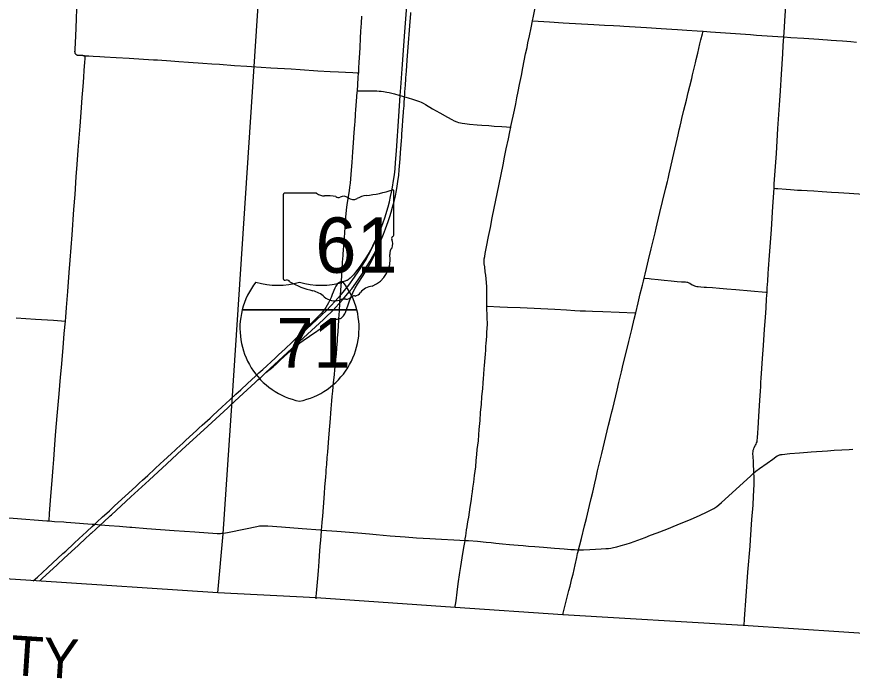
# Model space of a CAD drawing. Extents: x 1815539 to 1947826, y 273303 to 993194.
# Drawn here: x 1868609 to 1889640, y 855404 to 872057 of the extents above; entities that cross this region are included whole.
import ezdxf

# ---------------------------------------------------------------- set-up
doc = ezdxf.new("R2010")
doc.units = 0
for name, color, linetype in [('GM_X_Adjacent_County_Text', 7, 'Continuous'), ('GM_X_County', 7, 'Continuous'), ('GM_X_County_Road', 7, 'Continuous'), ('GM_X_Interchange_Ramps', 7, 'Continuous'), ('GM_X_Interstate_Route', 7, 'Continuous'), ('GM_X_Interstate_Shield', 7, 'Continuous'), ('GM_X_State_Route', 7, 'Continuous'), ('GM_X_Township', 7, 'Continuous'), ('GM_X_Township_Road', 7, 'Continuous'), ('SC_Shading3', 7, 'Continuous')]:
    doc.layers.add(name, color=color, linetype=linetype)

msp = doc.modelspace()

# ---------------------------------------------------------------- linework, layer by layer
at = {"layer": 'GM_X_County'}
msp.add_lwpolyline([(1890695, 856480), (1886895, 856734), (1882352, 856998), (1879641, 857188), (1876143, 857428), (1873671, 857558), (1869100, 857855), (1863977, 858188), (1861827, 858324), (1850615, 859080), (1848752, 859146), (1848787, 859601), (1848864, 860810), (1849106, 864311), (1849634, 872258), (1850017, 877290), (1850147, 879854), (1845959, 880135)], dxfattribs=at)
at = {"layer": 'GM_X_County_Road'}
for points in [[(1887918, 871548), (1887924, 871662), (1887953, 872087), (1887976, 872429), (1887990, 872658), (1888004, 872870), (1888017, 873050), (1888042, 873443), (1888071, 873901), (1888119, 874654), (1888128, 874784)], [(1881591, 871952), (1881615, 872067), (1881668, 872319), (1881683, 872399), (1881701, 872487), (1881717, 872568), (1881734, 872660), (1881750, 872737), (1881780, 872881), (1881800, 872979), (1881819, 873079), (1881833, 873160), (1881843, 873242), (1881852, 873340), (1881855, 873411)], [(1870298, 871074), (1870294, 871075), (1870289, 871076), (1870285, 871076), (1870282, 871076), (1870275, 871077), (1870264, 871078), (1870241, 871078), (1870169, 871081), (1870146, 871083), (1870141, 871084), (1870133, 871086), (1870126, 871089), (1870119, 871092), (1870112, 871096), (1870105, 871102), (1870098, 871108), (1870093, 871114), (1870089, 871121), (1870084, 871129), (1870081, 871137), (1870078, 871146), (1870077, 871153), (1870076, 871158), (1870076, 871164), (1870075, 871170), (1870075, 871179), (1870076, 871207), (1870077, 871235), (1870095, 871573), (1870103, 871769), (1870115, 872014), (1870126, 872244)], [(1881042, 869278), (1881045, 869291), (1881134, 869708), (1881169, 869868), (1881199, 870012), (1881232, 870173), (1881268, 870350), (1881314, 870575), (1881350, 870769), (1881384, 870946), (1881419, 871123), (1881453, 871283), (1881477, 871396), (1881513, 871572), (1881555, 871781), (1881591, 871952)], [(1881591, 871952), (1882016, 871925), (1882365, 871907), (1883139, 871858), (1883401, 871847), (1883626, 871836), (1883788, 871828), (1883887, 871823), (1884459, 871786), (1884826, 871761)], [(1884826, 871761), (1884966, 871751), (1885097, 871742), (1885244, 871732), (1885478, 871716), (1885735, 871700), (1885885, 871690)], [(1885694, 870900), (1885712, 870976), (1885750, 871136), (1885807, 871375), (1885830, 871471), (1885868, 871630), (1885885, 871690)], [(1887670, 867741), (1887677, 867850), (1887700, 868177), (1887729, 868618), (1887770, 869240), (1887808, 869829), (1887830, 870189), (1887856, 870614), (1887891, 871122), (1887904, 871334), (1887918, 871548)], [(1869835, 864397), (1869843, 864490), (1869862, 864735), (1869893, 865144), (1869930, 865619), (1869952, 865930), (1870002, 866568), (1870050, 867206), (1870077, 867582), (1870109, 868024), (1870132, 868335), (1870159, 868695), (1870204, 869301), (1870230, 869644), (1870258, 870020), (1870278, 870299), (1870295, 870528), (1870307, 870708), (1870323, 870904), (1870331, 871007), (1870332, 871017), (1870333, 871028), (1870333, 871032), (1870333, 871037), (1870333, 871040), (1870332, 871044), (1870332, 871045), (1870332, 871048), (1870331, 871050), (1870330, 871053), (1870329, 871055), (1870327, 871058), (1870326, 871060), (1870325, 871061), (1870323, 871063), (1870321, 871064), (1870319, 871066), (1870317, 871067), (1870315, 871068), (1870313, 871069), (1870310, 871070), (1870308, 871071), (1870298, 871074)], [(1870298, 871074), (1870424, 871069), (1870533, 871063), (1870699, 871054), (1870822, 871047), (1871116, 871029), (1871443, 871010), (1871803, 870988), (1872048, 870973), (1872150, 870968), (1872485, 870945), (1872686, 870930), (1872931, 870913), (1873291, 870888), (1873519, 870873), (1873716, 870860), (1874091, 870831), (1874402, 870810), (1874516, 870803)], [(1874516, 870803), (1875007, 870772), (1875514, 870742), (1875743, 870727), (1876184, 870698), (1876495, 870679), (1876707, 870666), (1876887, 870659), (1877067, 870651), (1877182, 870646), (1877216, 870645)], [(1884401, 865479), (1884424, 865573), (1884458, 865716), (1884513, 865939), (1884579, 866210), (1884651, 866513), (1884679, 866621), (1884706, 866733), (1884733, 866844), (1884766, 866988), (1884800, 867132), (1884865, 867402), (1884949, 867753), (1884988, 867913), (1885002, 867976), (1885032, 868104), (1885067, 868248), (1885126, 868503), (1885254, 869080), (1885283, 869208), (1885306, 869303), (1885334, 869415), (1885353, 869494), (1885403, 869701), (1885465, 869956), (1885513, 870147), (1885551, 870307), (1885598, 870498), (1885621, 870593), (1885694, 870900)], [(1880446, 864770), (1880445, 864839), (1880441, 865118), (1880441, 865256), (1880436, 865364), (1880425, 865461), (1880415, 865553), (1880404, 865637), (1880388, 865760), (1880378, 865837), (1880375, 865898), (1880378, 865959), (1880388, 866024), (1880401, 866097), (1880436, 866266), (1880487, 866526), (1880531, 866751), (1880580, 866992), (1880753, 867844), (1880849, 868326), (1880889, 868519), (1880930, 868728), (1880983, 868985), (1881019, 869162), (1881042, 869278)], [(1887494, 865122), (1887497, 865170), (1887500, 865235), (1887511, 865399), (1887526, 865595), (1887533, 865708), (1887559, 866050), (1887573, 866263), (1887603, 866704), (1887641, 867277), (1887670, 867741)], [(1884190, 864602), (1884252, 864855), (1884305, 865078), (1884359, 865302), (1884382, 865397), (1884401, 865479)], [(1887166, 860572), (1887164, 860625), (1887155, 860789), (1887150, 860871), (1887144, 860969), (1887141, 861068), (1887142, 861101), (1887145, 861134), (1887149, 861150), (1887153, 861166), (1887159, 861182), (1887173, 861212), (1887206, 861269), (1887221, 861298), (1887233, 861328), (1887242, 861359), (1887248, 861390), (1887254, 861455), (1887262, 861586), (1887268, 861701), (1887286, 861995), (1887312, 862404), (1887327, 862634), (1887335, 862748), (1887342, 862862), (1887349, 862961), (1887366, 863206), (1887382, 863451), (1887404, 863779), (1887432, 864188), (1887452, 864482), (1887469, 864728), (1887483, 864957), (1887494, 865122)], [(1880367, 863051), (1880377, 863199), (1880383, 863268), (1880391, 863382), (1880397, 863469), (1880406, 863567), (1880414, 863666), (1880419, 863752), (1880426, 863840), (1880432, 863919), (1880440, 864028), (1880446, 864115), (1880453, 864206), (1880455, 864322), (1880453, 864484), (1880446, 864770)], [(1868595, 864476), (1869081, 864445), (1869537, 864416), (1869835, 864397)], [(1869425, 859366), (1869437, 859552), (1869463, 859879), (1869479, 860092), (1869503, 860386), (1869527, 860714), (1869541, 860910), (1869571, 861286), (1869588, 861515), (1869606, 861727), (1869637, 862103), (1869675, 862561), (1869711, 862986), (1869732, 863231), (1869775, 863722), (1869807, 864081), (1869835, 864397)], [(1882749, 858641), (1882781, 858766), (1882823, 858927), (1882904, 859244), (1882948, 859428), (1883026, 859753), (1883068, 859929), (1883106, 860089), (1883158, 860312), (1883190, 860461), (1883229, 860629), (1883269, 860791), (1883333, 861063), (1883508, 861779), (1883548, 861938), (1883592, 862113), (1883612, 862192), (1883721, 862655), (1883766, 862846), (1883830, 863118), (1883877, 863309), (1883965, 863676), (1884016, 863883), (1884089, 864186), (1884150, 864441), (1884190, 864602)], [(1879893, 858874), (1879899, 858914), (1879910, 858992), (1879918, 859061), (1879931, 859139), (1879943, 859213), (1879959, 859293), (1879975, 859388), (1879986, 859464), (1880023, 859712), (1880035, 859806), (1880053, 859910), (1880067, 859997), (1880081, 860098), (1880092, 860193), (1880111, 860342), (1880134, 860505), (1880161, 860729), (1880175, 860889), (1880189, 861041), (1880201, 861164), (1880228, 861384), (1880242, 861531), (1880253, 861663), (1880270, 861893), (1880286, 862093), (1880305, 862302), (1880320, 862485), (1880339, 862702), (1880350, 862834), (1880360, 862959), (1880366, 863040), (1880367, 863051)], [(1887166, 860572), (1887216, 860614), (1887308, 860683), (1887494, 860818), (1887640, 860924), (1887720, 860982), (1887748, 861000), (1887777, 861016), (1887808, 861028), (1887824, 861033), (1887840, 861037), (1887873, 861041), (1888069, 861059), (1888315, 861078), (1888511, 861093), (1888609, 861101), (1889018, 861133), (1889182, 861145), (1889378, 861158), (1889558, 861167), (1889657, 861171)], [(1882749, 858641), (1882876, 858641), (1883037, 858646), (1883179, 858653), (1883316, 858659), (1883436, 858668), (1883501, 858674), (1883566, 858683), (1883630, 858695), (1883710, 858714), (1883820, 858744), (1883946, 858781), (1884055, 858817), (1884240, 858883), (1884425, 858950), (1884563, 859003), (1884731, 859068), (1884976, 859162), (1885236, 859265), (1885584, 859409), (1885793, 859503), (1885987, 859592), (1886107, 859652), (1886158, 859681), (1886205, 859710), (1886235, 859732), (1886284, 859770), (1886345, 859827), (1887081, 860494), (1887166, 860572)], [(1886918, 856737), (1886925, 856900), (1886968, 857475), (1887012, 858072), (1887069, 858727), (1887080, 858891), (1887115, 859398), (1887142, 859758), (1887156, 859987), (1887164, 860134), (1887171, 860293), (1887170, 860478), (1887166, 860572)], [(1861916, 859928), (1862629, 859873), (1863120, 859837), (1864150, 859761), (1864739, 859716), (1865507, 859658), (1865802, 859636), (1865998, 859622), (1866227, 859604), (1866505, 859582), (1866652, 859574), (1866832, 859561), (1867127, 859537), (1867486, 859512), (1868517, 859434), (1869367, 859370), (1869425, 859366)], [(1869425, 859366), (1869563, 859355), (1869793, 859339), (1869857, 859334)], [(1869857, 859334), (1869972, 859325), (1870512, 859285), (1870571, 859280), (1870708, 859269), (1870720, 859268), (1870937, 859253), (1871199, 859232), (1871452, 859211)], [(1871452, 859211), (1871509, 859207), (1871885, 859178), (1872572, 859126), (1873096, 859088), (1873652, 859052), (1873735, 859052), (1873770, 859055)], [(1873770, 859055), (1873817, 859059), (1873914, 859075), (1874364, 859169), (1874653, 859228), (1874683, 859233), (1874719, 859239), (1874747, 859242), (1874759, 859243), (1874778, 859244), (1874831, 859245), (1874929, 859242), (1875273, 859215), (1875796, 859173), (1876256, 859137), (1876281, 859135)], [(1876281, 859135), (1876663, 859106), (1877195, 859066), (1877490, 859039), (1877653, 859024), (1878012, 858994), (1878385, 858961), (1878670, 858941), (1879005, 858919), (1879153, 858913), (1879766, 858880), (1879893, 858874)], [(1879641, 857189), (1879648, 857220), (1879655, 857263), (1879670, 857355), (1879696, 857575), (1879722, 857780), (1879765, 858069), (1879788, 858222), (1879825, 858438), (1879867, 858697), (1879885, 858819), (1879893, 858874)], [(1879893, 858874), (1879982, 858869), (1880208, 858853), (1880429, 858833), (1880554, 858821), (1880668, 858808), (1880755, 858798), (1880836, 858790), (1881016, 858774), (1881229, 858754), (1881359, 858743), (1881425, 858738), (1881490, 858733), (1881654, 858720), (1881866, 858702), (1882144, 858679), (1882275, 858668), (1882389, 858660), (1882552, 858648), (1882650, 858642), (1882716, 858641), (1882749, 858641)], [(1882360, 857020), (1882365, 857041), (1882508, 857614), (1882537, 857726), (1882584, 857918), (1882612, 858029), (1882663, 858259), (1882703, 858442), (1882727, 858546), (1882745, 858623), (1882749, 858641)]]:
    msp.add_lwpolyline(points, dxfattribs=at)
at = {"layer": 'GM_X_Interchange_Ramps'}
for points in [[(1877739, 866630), (1877658, 866474), (1877610, 866370), (1877566, 866282), (1877511, 866181), (1877454, 866082), (1877393, 865984), (1877321, 865875), (1877256, 865781), (1877197, 865702), (1877136, 865625), (1877083, 865562), (1877039, 865513), (1877005, 865478), (1876980, 865456), (1876954, 865437), (1876926, 865420), (1876911, 865413), (1876896, 865407), (1876880, 865402), (1876864, 865399), (1876846, 865396), (1876780, 865386)], [(1876717, 864449), (1876728, 864453), (1876744, 864458), (1876759, 864464), (1876774, 864472), (1876787, 864481), (1876801, 864491), (1876813, 864502), (1876835, 864526), (1876855, 864553), (1876871, 864581), (1876884, 864612), (1876988, 864907), (1877035, 865030), (1877067, 865106), (1877097, 865165), (1877129, 865223), (1877190, 865321), (1877330, 865544), (1877420, 865696), (1877535, 865901), (1877630, 866090), (1877723, 866300)], [(1876780, 865386), (1876771, 865384), (1876755, 865381), (1876740, 865375), (1876725, 865368), (1876711, 865360), (1876698, 865350), (1876686, 865339), (1876675, 865327), (1876655, 865301), (1876639, 865273), (1876617, 865228), (1876551, 865061), (1876520, 864985), (1876494, 864925), (1876458, 864852), (1876426, 864795), (1876391, 864740), (1876353, 864686), (1876313, 864635), (1876269, 864586), (1876201, 864516), (1875824, 864151), (1875544, 863864)], [(1874882, 863099), (1875062, 863245), (1875136, 863311), (1875184, 863355), (1875233, 863400), (1875341, 863501), (1875498, 863646), (1875597, 863734), (1875673, 863797), (1875738, 863847), (1875818, 863905), (1875981, 864016), (1876376, 864285), (1876511, 864379), (1876552, 864406), (1876581, 864422), (1876595, 864429), (1876611, 864435), (1876631, 864439), (1876656, 864442), (1876684, 864445), (1876717, 864449)]]:
    msp.add_lwpolyline(points, dxfattribs=at)
at = {"layer": 'GM_X_Interstate_Route'}
for points in [[(1869023, 857856), (1869132, 857953), (1869385, 858187), (1869772, 858542), (1869844, 858608), (1870048, 858799), (1870193, 858932), (1870265, 858999), (1870374, 859099), (1870507, 859221), (1870571, 859280), (1870628, 859332), (1870772, 859465), (1870881, 859564), (1870942, 859620), (1871014, 859687), (1871074, 859743), (1871339, 859988), (1871604, 860232), (1871701, 860322), (1871772, 860389), (1871906, 860510), (1872087, 860677), (1872231, 860811), (1872304, 860877), (1872509, 861066), (1872593, 861145), (1872641, 861189), (1872787, 861322), (1872859, 861388), (1873052, 861567), (1873136, 861644), (1873196, 861700), (1873280, 861778), (1873341, 861833), (1873474, 861955), (1873546, 862023), (1873776, 862233), (1873872, 862322), (1873983, 862423), (1874126, 862554), (1874247, 862666), (1874415, 862822), (1874620, 863011), (1874704, 863089), (1874801, 863178), (1875115, 863466), (1875200, 863544), (1875368, 863700), (1875544, 863864), (1875913, 864199), (1876410, 864663), (1876625, 864894), (1876757, 865045), (1876783, 865075), (1876966, 865303), (1877113, 865499), (1877223, 865663), (1877384, 865923), (1877464, 866066), (1877549, 866221), (1877631, 866391), (1877739, 866630), (1877827, 866853), (1877884, 867020), (1877926, 867161), (1877959, 867274), (1877991, 867401), (1878021, 867529), (1878045, 867641), (1878070, 867770), (1878096, 867933), (1878115, 868079), (1878131, 868226), (1878145, 868390), (1878164, 868684), (1878228, 869551), (1878264, 870070), (1878278, 870272), (1878313, 870746), (1878330, 870975), (1878372, 871564), (1878428, 872333)], [(1878393, 870309), (1878407, 870521), (1878419, 870685), (1878440, 870963), (1878463, 871290), (1878503, 871830), (1878525, 872141), (1878526, 872162)], [(1878371, 870008), (1878373, 870039), (1878376, 870080), (1878381, 870145), (1878390, 870276), (1878393, 870309)], [(1878348, 869687), (1878351, 869736), (1878357, 869818), (1878363, 869900), (1878371, 870008)], [(1876975, 865128), (1877043, 865211), (1877201, 865430), (1877316, 865592), (1877499, 865892), (1877609, 866089), (1877723, 866300), (1877753, 866369), (1877785, 866444), (1877841, 866581), (1877894, 866719), (1877928, 866811), (1877961, 866904), (1878001, 867028), (1878035, 867138), (1878070, 867264), (1878106, 867407), (1878139, 867551), (1878165, 867680), (1878185, 867792), (1878202, 867906), (1878224, 868068), (1878238, 868199), (1878261, 868477), (1878273, 868640), (1878293, 868935), (1878299, 869033), (1878304, 869098), (1878321, 869311), (1878330, 869442), (1878345, 869654), (1878348, 869687)], [(1876614, 864715), (1876616, 864717), (1876744, 864855), (1876819, 864937), (1876975, 865128)], [(1870992, 859518), (1871483, 859969), (1871941, 860392), (1872388, 860803), (1872774, 861159), (1873317, 861659), (1873920, 862215), (1873973, 862265), (1874210, 862482), (1874608, 862849), (1874681, 862916), (1874741, 862971), (1874826, 863048), (1874882, 863099), (1875427, 863601), (1876330, 864435), (1876614, 864715)], [(1870487, 859053), (1870493, 859058), (1870601, 859158), (1870720, 859268), (1870794, 859336), (1870963, 859492), (1870992, 859518)], [(1869179, 857847), (1869251, 857912), (1869624, 858258), (1869805, 858424), (1870070, 858669), (1870155, 858747), (1870360, 858936), (1870432, 859003), (1870487, 859053)]]:
    msp.add_lwpolyline(points, dxfattribs=at)
at = {"layer": 'GM_X_Interstate_Shield'}
for p, q in [((1874284, 864676), (1877170, 864676)), ((1877170, 864676), (1874284, 864676)), ((1877170, 864676), (1874284, 864676))]:
    msp.add_line(p, q, dxfattribs=at)
for centre, start, end in [((1876102, 864216), 141.669, 165.8066), ((1875179, 867172), 253.0091, 286.9909), ((1876275, 867172), 253.0091, 286.9909), ((1875352, 864216), 14.1934, 38.331), ((1876102, 864216), 165.8066, 258.463), ((1875352, 864216), 281.537, 14.1934)]:
    msp.add_arc(centre, 1875, start, end, dxfattribs=at)
at = {"layer": 'GM_X_State_Route'}
for points in [[(1876826, 866049), (1876829, 866090), (1876849, 866385), (1876865, 866614), (1876887, 866908), (1876904, 867104), (1876922, 867267), (1876937, 867381), (1876981, 867672), (1876995, 867770), (1877007, 867868), (1877034, 868195), (1877050, 868391), (1877070, 868652), (1877087, 868881), (1877106, 869143), (1877120, 869338), (1877126, 869421), (1877138, 869580), (1877140, 869613), (1877148, 869716), (1877163, 869928), (1877180, 870157), (1877183, 870192), (1877207, 870517), (1877215, 870632), (1877216, 870645), (1877223, 870762), (1877231, 870910), (1877243, 871139), (1877252, 871286), (1877265, 871516), (1877274, 871696), (1877285, 871892), (1877296, 872072)], [(1876679, 863895), (1876685, 863983), (1876689, 864037), (1876696, 864130), (1876715, 864422), (1876717, 864449), (1876730, 864651), (1876743, 864847), (1876744, 864855), (1876757, 865045), (1876765, 865174), (1876780, 865386), (1876781, 865403), (1876801, 865698), (1876813, 865878), (1876826, 866049)], [(1876144, 857406), (1876149, 857465), (1876155, 857548), (1876187, 857916), (1876203, 858112), (1876220, 858341), (1876232, 858488), (1876251, 858733), (1876261, 858881), (1876279, 859106), (1876281, 859135), (1876289, 859220), (1876297, 859335), (1876310, 859481), (1876347, 859935), (1876356, 860066), (1876368, 860212), (1876387, 860474), (1876395, 860572), (1876402, 860653), (1876412, 860784), (1876426, 860964), (1876436, 861095), (1876465, 861454), (1876487, 861748), (1876503, 861944), (1876514, 862080), (1876521, 862188), (1876530, 862287), (1876538, 862385), (1876549, 862499), (1876563, 862630), (1876586, 862841), (1876607, 863054), (1876620, 863170), (1876635, 863308), (1876643, 863426), (1876656, 863559), (1876667, 863721), (1876679, 863895)]]:
    msp.add_lwpolyline(points, dxfattribs=at)
at = {"layer": 'GM_X_Township'}
msp.add_lwpolyline([(1873671, 857558), (1873806, 859043), (1874029, 862389), (1874586, 870801), (1874844, 874776), (1875147, 880018), (1875287, 882532), (1875268, 882593), (1875339, 883824), (1877996, 883681), (1878453, 883649), (1879771, 883544), (1879947, 883530), (1880714, 883463), (1881064, 883424), (1881619, 883383), (1882389, 883337), (1886519, 883080), (1888679, 882953), (1894036, 882664)], dxfattribs=at)
at = {"layer": 'GM_X_Township_Road'}
for points in [[(1885885, 871690), (1886068, 871676), (1887078, 871606), (1887226, 871595), (1887898, 871549), (1887918, 871548)], [(1887918, 871548), (1888097, 871537), (1888424, 871515), (1888670, 871498), (1888801, 871490), (1888899, 871484), (1889013, 871477), (1889112, 871469), (1889242, 871459), (1889390, 871448), (1889503, 871439)], [(1889503, 871439), (1889602, 871431), (1889749, 871420)], [(1877183, 870192), (1877195, 870192), (1877264, 870192), (1877425, 870189), (1877615, 870189), (1877672, 870188), (1877728, 870187), (1877786, 870180), (1877837, 870174), (1877881, 870167), (1877926, 870160), (1877985, 870147), (1878118, 870112), (1878228, 870080), (1878264, 870070), (1878320, 870055), (1878373, 870039), (1878399, 870031), (1878464, 870012), (1878575, 869979), (1878700, 869940), (1878747, 869924), (1878792, 869905), (1878836, 869883), (1878894, 869851), (1879077, 869742), (1879262, 869636), (1879448, 869531), (1879563, 869469), (1879622, 869440), (1879683, 869415), (1879729, 869398), (1879776, 869385), (1879824, 869375), (1879889, 869365), (1880003, 869354), (1880199, 869339), (1880313, 869331), (1880493, 869316), (1880624, 869305), (1880820, 869292), (1880935, 869285), (1881022, 869280), (1881042, 869278)], [(1887670, 867741), (1887682, 867740), (1887720, 867737), (1887766, 867733), (1887972, 867716), (1888088, 867706), (1888176, 867698), (1888264, 867693), (1888364, 867688), (1888507, 867679), (1888673, 867670), (1888883, 867658), (1889113, 867643), (1889291, 867630), (1889560, 867612), (1889920, 867588), (1890068, 867578), (1890073, 867578)], [(1884401, 865479), (1884430, 865476), (1884528, 865465), (1884577, 865461), (1884757, 865442), (1884904, 865429), (1885084, 865411), (1885231, 865396), (1885345, 865386), (1885443, 865381), (1885476, 865377), (1885492, 865373), (1885507, 865368), (1885522, 865362), (1885551, 865346), (1885607, 865312), (1885636, 865296), (1885666, 865284), (1885698, 865275), (1885730, 865268), (1885762, 865262), (1885827, 865256), (1885909, 865251), (1885975, 865249), (1886122, 865238), (1886302, 865224), (1886482, 865208), (1886711, 865189), (1887464, 865124), (1887494, 865122)], [(1880446, 864770), (1880459, 864770), (1880770, 864758), (1880963, 864750), (1881280, 864737), (1882157, 864696), (1882446, 864678), (1882658, 864663), (1882787, 864656), (1882927, 864653), (1883100, 864647), (1883361, 864637), (1883772, 864617), (1884167, 864603), (1884190, 864602)]]:
    msp.add_lwpolyline(points, dxfattribs=at)
at = {"layer": 'SC_Shading3'}
for p, q in [((1875315, 867576), (1875315, 865463)), ((1876158, 867613), (1875342, 867613)), ((1878099, 866560), (1878099, 867665)), ((1878099, 866560), (1878099, 866560))]:
    msp.add_line(p, q, dxfattribs=at)
for centre, radius, start, end in [((1875347, 867581), 32.3, 98.1301, 188.1301), ((1876352, 867858), 313, 231.6195, 271.1119), ((1876456, 866426), 1123, 80.4867, 94.9883), ((1877484, 866967), 594, 97.3462, 120.7689), ((1877108, 870494), 2953, 275.8445, 288.9065), ((1878068, 867670), 31, 351.8621, 97.738), ((1876711, 867592), 90.3, 219.7921, 297.1024), ((1876843, 867348), 188, 54.4667, 119.1411), ((1877085, 867683), 226, 233.8562, 294.8282), ((1878092, 866479), 48, 107.944, 210.337), ((1878066, 866555), 33.2, 289.6038, 7.7341), ((1877787, 866339), 288, 340.033, 23.6496), ((1878210, 866097), 210, 136.8065, 186.9296), ((1877273, 865956), 739, 292.3089, 8.9858), ((1875347, 865459), 32.5, 171.9584, 258.3066), ((1875352, 865675), 248, 267.339, 280.6039), ((1875403, 865341), 89.5, 29.7484, 93.2717), ((1876534, 867240), 2132, 240.4129, 257.1985), ((1877584, 864870), 404, 94.4031, 142.5768), ((1875898, 864514), 667, 47.1842, 75.836), ((1877099, 864968), 63.5, 65.7517, 132.6484), ((1877072, 865258), 239, 282.8732, 323.2771), ((1876619, 865331), 423, 230.7004, 286.2918), ((1876864, 864600), 348, 85.6951, 111.2099), ((1876895, 865173), 226, 268.777, 315.5493)]:
    msp.add_arc(centre, radius, start, end, dxfattribs=at)

# ---------------------------------------------------------------- texts
at = {"layer": 'GM_X_Adjacent_County_Text'}
msp.add_text('DELAWARE COUNTY', height=1000, rotation=356.2231, dxfattribs=at).set_placement((1856635, 856270))
at = {"layer": 'GM_X_Interstate_Shield'}
msp.add_text('71', height=1250, dxfattribs=at).set_placement((1875149, 863223))
at = {"layer": 'SC_Shading3'}
msp.add_text('61', height=1392.2, dxfattribs=at).set_placement((1876125, 865612))

doc.saveas('drawing.dxf')
